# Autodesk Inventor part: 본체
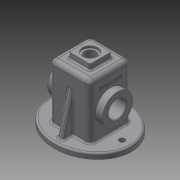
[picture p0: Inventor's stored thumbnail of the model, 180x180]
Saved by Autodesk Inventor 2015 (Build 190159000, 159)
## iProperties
Created: 2017-07
Part Number: 본체
Material: 일반
Document SubType Name: Modeling
Designer: C03
Density: 1 g/cm^3
Appearance: 기본값
Author: C03
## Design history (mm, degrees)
sketch "스케치1"
  geometry: L1 (0, 0)-(0, 65); L2 (0, 0)-(-75, 0); 2 further points; 1 other entity
  constraints: 4 end point, 2 coincident, 2 horizontal, 1 vertical, 4 other
  dimensions: "d1" = 65 distance of L1.start L1.end; "d2" = 75 distance of L1.start L2.end
extrude "돌출1" new body sketch "스케치1" distance "d3" = 10; taper "d4" = 0 deg
sketch "스케치2"
  geometry: L1 (-37, 37)-(37, 37); L2 (37, 37)-(37, -37); L3 (37, -37)-(-37, -37); L4 (-37, -37)-(-37, 37); L5 (-37, 37)-(37, -37); L6 (37, 37)-(-37, -37); 1 further point
  constraints: 12 end point, 2 midpoint, 2 parallel, 1 horizontal, 1 perpendicular
  dimensions: "d5" = 74 distance of L2.end L3.end; "d6" = 74 distance of L1.end L2.end
extrude "돌출2" join sketch "스케치2" distance "d7" = 100; taper "d8" = 0 deg
sketch "스케치4"
  geometry: L1 (32, -32)-(-32, -32); L2 (-32, -32)-(-32, 32); L3 (-32, 32)-(32, 32); L4 (32, 32)-(32, -32); L5 (32, -32)-(-32, 32); L6 (-32, -32)-(32, 32); 1 further point
  constraints: 12 end point, 2 midpoint, 2 parallel, 1 horizontal, 1 perpendicular
  dimensions: "d11" = 64 distance of L2.end L3.end; "d12" = 64 distance of L1.end L2.end
extrude "돌출3" cut sketch "스케치4" distance "d13" = 105; taper "d14" = 0 deg
node "작업 평면1"
sketch "스케치5"
  geometry: L1 (0, 0)-(0, 100) reference; L2 (-13, 45)-(-13, 72.5); L3 (-13, 72.5)-(5, 72.5); L4 (5, -10)-(5, 95) reference; L5 (5, 45)-(12, 45); L6 (12, 45)-(12, 65.5); L7 (5, 72.5)-(12, 65.5); L8 (5, 72.5)-(12, 72.5); L9 (87, 72.5)-(69, 72.5); L10 (69, 72.5)-(62, 65.5); L11 (62, 45)-(62, 65.5); L12 (87, 45)-(87, 72.5); L13 (-13, 45)-(12, 45); L14 (62, 45)-(87, 45); 1 further point
  constraints: 24 end point, 3 horizontal, 3 parallel, 3 perpendicular, 3 point on line, 1 vertical
  dimensions: "d16" = 100 distance of L2.start L12.start; "d17" = 27.5 distance of L2.start L2.end; "d18" = 18 distance of L2.end L3.end; "d21" = 7 distance of L5.start L5.end; "d22" = 45 deg angle of L7 L8; "d23" = 13 distance between parallel lines of L1 L2; "d24" = 57 distance between parallel lines of L11 L4; "d26" = 35.70889 distance from line of point (37, -10) L10; "d27" = 27.5 distance from line of L11.start L9; "d28" = 82 distance between parallel lines of L12 L4; "d29" = 82.5 distance from line of point (37, -10) L9
revolve "회전1" sketch "스케치5" stored, may be unused: angle "d30" = 90 deg
sketch "스케치6"
  geometry: C1 r 27.5 at (0, 0) reference; C2 r 20.5 at (0, 0) reference; C3 r 16 at (0, 0); 1 further point
  constraints: 1 centre point, 1 coincident
  dimensions: "d31" = 32 diameter of C3
extrude "돌출4" cut sketch "스케치6" stored distance "d32" = 105; taper "d33" = 0 deg
sketch "스케치7"
  geometry: L1 (-17, 20)-(17, 20); L2 (20, 17)-(20, -17); L3 (17, -20)-(-17, -20); L4 (-20, -17)-(-20, 17); L5 (-20, 20)-(20, -20); L6 (20, 20)-(-20, -20); A1 r 3 centre (-17, 17) between (-17, 20) and (-20, 17); A2 r 3 centre (17, 17) between (20, 17) and (17, 20); A3 r 3 centre (17, -17) between (17, -20) and (20, -17); A4 r 3 centre (-17, -17) between (-20, -17) and (-17, -20); 1 further point
  constraints: 12 end point, 8 point on circle, 8 point on line, 8 tangent, 4 centre point, 3 equal radius, 2 midpoint, 2 parallel, 1 horizontal, 1 perpendicular
  dimensions: "d34" = 40 distance of L5.end L6.end; "d35" = 40 distance of L6.start L5.end; "d49" = 3 radius of A1
extrude "돌출7" join sketch "스케치7" distance "d50" = 10; taper "d51" = -5 deg
sketch "스케치11"
  geometry: 2 further points
  constraints: 1 coincident
hole "구멍2" sketch "스케치11" at (0, 0) diameter "d52" = 21; stored, may be unused: countersink angle "d56" = 90 deg, drill point angle "d58" = 0 deg; dims "d53" = 6, "d54" = 28, "d55" = 4, "d57" = 15
node "작업 평면2"
sketch "스케치12"
  geometry: L1 (-3.558, -18.887)-(80.394, 2.044) reference; L2 (-3.558, -18.887)-(-3.558, 2.044); L3 (-3.558, 2.044)-(80.394, 2.044)
  constraints: 6 end point, 1 perpendicular, 1 vertical, 1 other
  dimensions: "d65" = 86.52141 distance of L1.end L1.start
extrude "돌출8" join sketch "스케치12" stored distance "d66" = 10; taper "d67" = 0 deg
sketch "스케치13"
  geometry: L1 (0, 0)-(58, 0); L2 (0, 0)-(-58, 0); 2 further points
  constraints: 4 end point, 2 coincident, 2 horizontal
  dimensions: "d68" = 58 distance of L1.start L1.end; "d69" = 58 distance of L1.start L2.end
hole "구멍3" sketch "스케치13" at (58, 0), (-58, 0) diameter "d70" = 10; stored, may be unused: countersink angle "d74" = 90 deg, drill point angle "d76" = 0 deg; dims "d71" = 6, "d72" = 28, "d73" = 4, "d75" = 15
sketch "스케치14"
  geometry: L1 (0, 0)-(-22.5, 0); C1 r 16 at (0, 0) reference; 2 further points
  constraints: 2 end point, 1 coincident, 1 horizontal
  dimensions: "d77" = 22.5 distance of L1.start L1.end
hole "구멍4" sketch "스케치14" at (-22.5, 0) diameter "d78" = 3.242; stored, may be unused: countersink angle "d82" = 90 deg, drill point angle "d84" = 118 deg; dims "d79" = 8, "d80" = 4, "d81" = 4, "d83" = 10
sketch "스케치15"
  geometry: L1 (0, 0)-(22.5, 0); C1 r 16 at (0, 0) reference; C2 r 27.5 at (0, 0) reference; C3 r 1.621 at (22.5, 0) reference; 2 further points
  constraints: 2 end point, 1 coincident, 1 horizontal
  dimensions: "d88" = 22.5 distance of L1.start L1.end (derived)
hole "구멍5" sketch "스케치15" at (22.5, 0) diameter "d89" = 3.242; stored, may be unused: countersink angle "d93" = 90 deg, drill point angle "d95" = 118 deg; dims "d90" = 8, "d91" = 4, "d92" = 4, "d94" = 10
fillet "모깎기3" dims "d99" = 0.5, "d100" = 3
fillet "모깎기4" dims "d101" = 8
fillet "모깎기5" dims "d102" = 3
fillet "모깎기6" dims "d103" = 3
fillet "모깎기7" dims "d104" = 3
chamfer "모따기1" distance "d105" = 1; stored, may be unused: second distance "d106" = 2, angle "d107" = 45 deg
sketch "스케치16"
  geometry: L1 (-18, 46)-(-18, 12) reference; L2 (89, 66)-(0, 66) reference; 2 further points
  constraints: 1 other
  dimensions: "d108" = 30 distance from line of L1 point (12, 29); "d109" = 37 distance from line of point (12, 29) L2
feature "엠보싱1" sketch "스케치16" dims "d1" = 65, "d2" = 75, "d12" = 64, "d110" = 0.5, "d111" = 0
node "솔리드1"
mirror "대칭1"
pattern_circular "원형 패턴1" dims angle "d86" = 360 deg
pattern_circular "원형 패턴2" dims angle "d97" = 360 deg
node "투영된 루프1"
node "투영된 루프4"
other parameters: "d15" = 55, "d25" = 27.5
